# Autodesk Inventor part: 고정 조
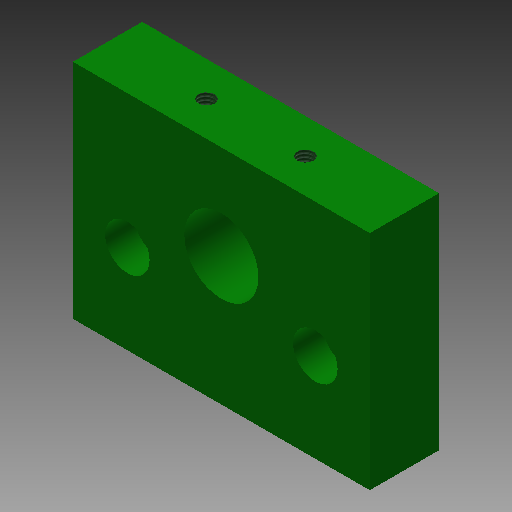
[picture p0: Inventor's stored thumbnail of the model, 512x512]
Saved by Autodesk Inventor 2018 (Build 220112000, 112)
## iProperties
Created: 2020-03
Part Number: 고정 조
Material: 알루미늄 6061
Document SubType Name: Modeling
Designer: mduedu
Density: 2.71 g/cm^3
Mass: 90.2037 g
Surface Area: 96.6422 cm^2
Volume: 33.2855 cm^3
Appearance: 진녹색
Author: mduedu
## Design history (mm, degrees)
sketch "스케치1"
  geometry: L1 (-30, 0)-(30, 0); L2 (30, 0)-(30, 48); L3 (30, 48)-(-30, 48); L4 (-30, 48)-(-30, 0); 2 further points
  constraints: 8 end point, 2 parallel, 1 coincident, 1 horizontal, 1 midpoint, 1 perpendicular
  dimensions: "d0" = 60 distance of L1.start L1.end; "d2" = 48 distance of L1.end L2.end
extrude "돌출1" new body sketch "스케치1" distance "d3" = 14; taper "d4" = 0 deg
sketch "스케치2"
  geometry: 3 further points
  constraints: 1 horizontal alignment
  dimensions: "d5" = 7 vertical distance of point (52, 7) point (30, 0); "d6" = 22 horizontal distance of point (8, 7) point (30, 0); "d7" = 44 distance of point (52, 7) point (8, 7)
hole "구멍1" sketch "스케치2" at (8, 7), (52, 7) diameter "d8" = 3.242; stored, may be unused: countersink angle "d12" = 90 deg, drill point angle "d14" = 118 deg; dims "d9" = 8, "d10" = 4, "d11" = 2, "d13" = 10
sketch "스케치3"
  geometry: L1 (30, 0)-(-30, 0) reference; 3 further points
  constraints: 1 midpoint, 1 vertical alignment
  dimensions: "d15" = 26 distance of point (0, 0) point (0, 26)
hole "구멍2" sketch "스케치3" at (0, 26) diameter "d16" = 15; stored, may be unused: countersink angle "d20" = 90 deg, drill point angle "d22" = 118 deg; dims "d17" = 8, "d18" = 20, "d19" = 3, "d21" = 10
sketch "스케치4"
  geometry: L1 (30, 0)-(-30, 0) reference; 5 further points
  constraints: 1 coincident, 1 horizontal alignment, 1 midpoint
  dimensions: "d23" = 18 vertical distance of point (19, 18) point (0, 0); "d24" = 19 horizontal distance of point (-19, 18) point (0, 0); "d25" = 38 distance of point (19, 18) point (-19, 18)
hole "구멍7" sketch "스케치4" at (-19, 18), (19, 18) diameter "d65" = 4.5; stored, may be unused: countersink angle "d69" = 90 deg, drill point angle "d71" = 118 deg; dims "d66" = 6, "d67" = 8, "d68" = 4.4, "d70" = 8
hole "구멍8" diameter "d74" = 9; stored, may be unused: countersink angle "d78" = 90 deg, drill point angle "d80" = 0 deg; dims "d72" = 10, "d73" = 10, "d75" = 6, "d76" = 8, "d77" = 4.4, "d79" = 6
hole "구멍9" diameter "d83" = 9; stored, may be unused: countersink angle "d87" = 90 deg, drill point angle "d89" = 0 deg; dims "d81" = 10, "d82" = 10, "d84" = 6, "d85" = 8, "d86" = 4.4, "d88" = 6
sketch "스케치7"
  geometry: L1 (-18, 48)-(18, 48); L2 (18, 48)-(18, 45); L3 (18, 45)-(-18, 45); L4 (-18, 45)-(-18, 48); L5 (30, 48)-(-30, 48) reference; L6 (-30, 0)-(30, 0) reference; 5 further points
  constraints: 8 end point, 2 midpoint, 2 parallel, 1 collinear, 1 horizontal, 1 perpendicular, 1 vertical alignment
  dimensions: "d50" = 3 distance of L1.end L2.end; "d52" = 36 distance of L1.start L1.end
extrude "돌출2" cut sketch "스케치7" extent not by distance; stored distance "d53" = 10; taper "d54" = 0 deg
sketch "스케치8"
  geometry: 3 further points
  constraints: 1 horizontal alignment
  dimensions: "d55" = 7 vertical distance of point (28, 7) point (18, 14); "d56" = 10 horizontal distance of point (8, 7) point (18, 14); "d57" = 20 distance of point (28, 7) point (8, 7)
hole "구멍6" sketch "스케치8" at (8, 7), (28, 7) diameter "d58" = 3.242; stored, may be unused: countersink angle "d62" = 90 deg, drill point angle "d64" = 118 deg; dims "d59" = 6, "d60" = 4, "d61" = 2, "d63" = 8
sketch "스케치9"
  geometry: L1 (0, 14)-(0, 0) reference; L2 (36, 0)-(0, 0) reference; L3 (48, 0)-(36, 0) reference; L4 (48, 14)-(48, 0) reference; L5 (36, 14)-(48, 14) reference; L6 (36, 0)-(36, 14) reference; L7 (0, 14)-(36, 14) reference; L8 (-12, 14)-(0, 14) reference; L9 (-12, 0)-(-12, 14) reference; L10 (0, 0)-(-12, 0) reference; C1 r 1.621 at (8, 7) reference; C2 r 1.621 at (28, 7) reference; 1 further point
extrude "돌출3" cut sketch "스케치9" extent not by distance; stored distance "d90" = 10; taper "d91" = 0 deg
node "솔리드1"
node "절단 모서리 투영1"
